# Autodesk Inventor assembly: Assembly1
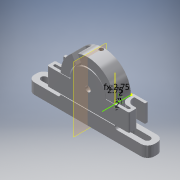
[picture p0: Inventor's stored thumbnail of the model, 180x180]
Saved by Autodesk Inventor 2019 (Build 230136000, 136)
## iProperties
Created: 2019-05
Part Number: Assembly1
Document SubType Name: Assembly
Designer: Chloe
Author: Chloe
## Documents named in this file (3)
- C:\Users\Chloe\Desktop\Design files\2mm Rb cell holder\Adobe Inventor format\Assembled 2mm Rb cell holder.iam
- C:\Users\Chloe\Desktop\Design files\2mm Rb cell holder\Adobe Inventor format\2mm Rb cell holder.ipt
- C:\Users\Chloe\Desktop\Design files\2mm Rb cell holder\Adobe Inventor format\2mm Rb cell holder cover.ipt
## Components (2 placed, 2 different names)
1. 2mm Rb cell holder:1
2. 2mm Rb cell holder cover:1
